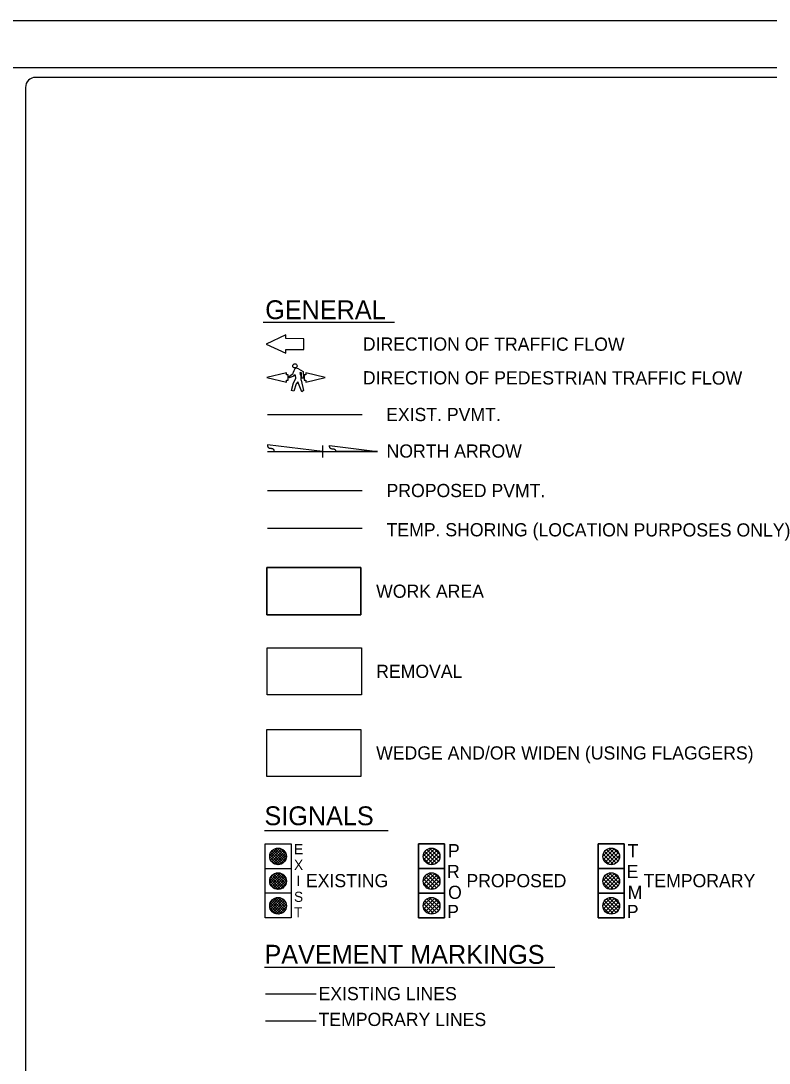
# Model space of a CAD drawing. Extents: x 0 to 1868, y 0 to 1100.
# Drawn here: x 733 to 1130, y 547 to 1100 of the extents above; entities that cross this region are included whole.
import ezdxf

# ---------------------------------------------------------------- set-up
doc = ezdxf.new("R2010")
doc.units = 0
for name, color, linetype in [('Exist Utilities Power Test Hole SUE LOS A CELL', 7, 'Continuous'), ('Exist Utilities Sanitary Sewer Test Hole SUE LOS A CELL', 7, 'Continuous'), ('Exist Utilities Telephone Test Hole SUE LOS A CELL', 7, 'Continuous'), ('P_RDY_Easement_Permanent_Drainage_Utility', 7, 'Continuous'), ('P_RDY_ROW_Permanent_Easement_CELL', 7, 'Continuous'), ('P_RDY_WCC_CELL', 7, 'Continuous')]:
    doc.layers.add(name, color=color, linetype=linetype)

msp = doc.modelspace()

# ---------------------------------------------------------------- linework, layer by layer
at = {"layer": 'Exist Utilities Power Test Hole SUE LOS A CELL'}
for p, q in [((862.52, 663.4), (876.32, 663.4)), ((862.52, 650.3), (862.52, 663.4)), ((864.99, 657.02), (869.1, 661.12)), ((865.09, 655.7), (870.41, 661.02)), ((865.47, 654.67), (871.45, 660.64)), ((865.52, 658.81), (871.53, 652.8)), ((865.73, 659.17), (866.95, 660.38)), ((866.04, 653.82), (872.3, 660.08)), ((866.1, 659.64), (872.36, 653.38)), ((866.77, 653.14), (872.98, 659.35)), ((866.84, 660.31), (873.03, 654.12)), ((867.67, 652.62), (873.5, 658.45)), ((867.76, 660.81), (873.53, 655.04)), ((868.88, 661.1), (873.82, 656.16)), ((870.36, 661.03), (873.75, 657.65)), ((876.32, 663.4), (876.32, 650.3)), ((864.98, 656.52), (869.23, 652.26)), ((865.12, 657.8), (870.52, 652.4)), ((865.54, 654.55), (867.27, 652.82)), ((868.77, 652.31), (873.81, 657.35)), ((870.21, 652.33), (873.79, 655.91)), ((862.52, 650.3), (876.32, 650.3)), ((862.52, 637.2), (862.52, 650.3)), ((864.98, 643.64), (869.38, 648.04)), ((865.15, 642.39), (870.62, 647.87)), ((865.39, 645.47), (867.55, 647.62)), ((865.57, 641.4), (871.62, 647.45)), ((867.04, 647.34), (873.16, 641.22)), ((867.99, 647.8), (873.62, 642.17)), ((869.18, 648.03), (873.85, 643.36)), ((870.81, 647.81), (873.63, 644.99)), ((876.32, 650.3), (876.32, 637.2)), ((864.98, 643.74), (869.56, 639.16)), ((865.19, 644.94), (870.76, 639.37)), ((865.26, 642.04), (867.86, 639.44)), ((865.63, 645.92), (871.74, 639.81)), ((866.16, 640.58), (872.44, 646.85)), ((866.25, 646.71), (872.53, 640.43)), ((866.93, 639.93), (873.09, 646.09)), ((867.86, 639.44), (873.57, 645.16)), ((869.01, 639.18), (873.84, 644.01)), ((870.55, 639.31), (873.71, 642.47)), ((876.32, 637.2), (862.52, 637.2)), ((862.52, 624.1), (862.52, 637.2)), ((876.32, 637.2), (876.32, 624.1)), ((864.99, 630.84), (869.76, 626.07)), ((865.01, 631), (868.92, 634.91)), ((865.06, 629.64), (870.27, 634.85)), ((865.24, 632), (870.92, 626.32)), ((865.42, 628.58), (871.34, 634.5)), ((865.72, 632.94), (871.86, 626.8)), ((865.96, 627.71), (872.2, 633.95)), ((866.36, 633.71), (872.63, 627.44)), ((866.68, 627.01), (872.91, 633.24)), ((867.17, 634.32), (873.24, 628.25)), ((867.55, 626.47), (873.44, 632.37)), ((868.15, 634.75), (873.67, 629.23)), ((868.63, 626.13), (873.78, 631.29)), ((869.38, 634.94), (873.86, 630.46)), ((871.14, 634.59), (873.51, 632.22)), ((865.16, 629.26), (868.18, 626.24)), ((870.01, 626.1), (873.82, 629.91)), ((876.32, 624.1), (862.52, 624.1))]:
    msp.add_line(p, q, dxfattribs=at)
for centre in [(869.42, 656.7), (869.42, 643.6), (869.42, 630.5)]:
    msp.add_circle(centre, 4.44, dxfattribs=at)
at = {"layer": 'Exist Utilities Sanitary Sewer Test Hole SUE LOS A CELL'}
msp.add_lwpolyline([(0, 0), (1688, 0), (1688, 1100), (0, 1100)], close=True, dxfattribs=at)
at = {"layer": 'Exist Utilities Telephone Test Hole SUE LOS A CELL'}
msp.add_line((862.82, 583.78), (889.62, 583.78), dxfattribs=at)
at = {"layer": 'P_RDY_Easement_Permanent_Drainage_Utility'}
msp.add_line((863.81, 830.84), (914, 830.84), dxfattribs=at)
at = {"layer": 'P_RDY_ROW_Permanent_Easement_CELL'}
for p, q in [((1652.71, 1075), (173.28, 1075)), ((1652.71, 1070), (740.76, 1070)), ((735.48, 1064.72), (735.48, 35.28)), ((861.5, 940.08), (931.19, 940.08)), ((873.53, 933.35), (863.18, 928.49)), ((873.52, 931.38), (873.53, 933.35)), ((883.12, 931.37), (873.52, 931.38)), ((883.12, 925.58), (883.12, 931.37)), ((863.18, 928.49), (873.52, 923.61)), ((873.52, 923.61), (873.52, 925.58)), ((873.52, 925.58), (883.12, 925.58)), ((873.86, 913.18), (863.52, 910.75)), ((873.86, 912.19), (873.86, 913.18)), ((875.03, 911.21), (877.52, 912.84)), ((877.52, 912.84), (877.68, 913.83)), ((880.31, 915.36), (882.81, 913.87)), ((881.9, 913.22), (881.09, 913.38)), ((882.13, 910.4), (881.9, 913.22)), ((882.81, 913.87), (882.84, 910.4)), ((894.47, 910.74), (884.14, 913.18)), ((884.14, 913.18), (884.14, 912.19)), ((863.52, 910.75), (873.85, 908.31)), ((873.85, 908.31), (873.85, 909.3)), ((873.85, 909.3), (874.78, 909.29)), ((874.79, 912.19), (873.86, 912.19)), ((874.78, 909.29), (874.79, 912.19)), ((875.42, 910.66), (875.03, 911.21)), ((877.7, 911.41), (875.42, 910.66)), ((876.52, 903.95), (877.59, 908.01)), ((877.59, 908.01), (878.82, 910.27)), ((878.48, 912.13), (877.7, 911.41)), ((879.02, 907.45), (877.85, 903.53)), ((879.99, 908.43), (879.02, 907.45)), ((881.96, 903.24), (879.99, 908.43)), ((881.66, 909.33), (882.94, 903.92)), ((882.84, 910.4), (882.13, 910.4)), ((884.14, 912.19), (883.2, 912.19)), ((883.2, 912.19), (883.2, 909.3)), ((883.2, 909.3), (884.13, 909.29)), ((884.13, 908.31), (894.47, 910.74)), ((884.13, 909.29), (884.13, 908.31)), ((877.85, 903.53), (876.52, 903.95)), ((882.94, 903.92), (881.96, 903.24)), ((863.81, 891.19), (914.01, 891.15)), ((893.04, 871.48), (863.82, 875.07)), ((893.04, 874.62), (893.04, 868.35)), ((896.76, 874.61), (922.27, 871.48)), ((863.82, 871.48), (922.27, 871.48)), ((867.28, 871.49), (893.04, 871.48)), ((922.27, 871.48), (900.07, 871.49)), ((863.81, 850.87), (914, 850.83)), ((863.4, 724.09), (913.4, 724.09)), ((863.4, 699.09), (863.4, 724.09)), ((913.4, 699.09), (863.4, 699.09)), ((862.2, 670.41), (927.79, 670.41)), ((946.5, 656.8), (950.8, 661.1)), ((946.85, 655), (952.6, 660.8)), ((953.5, 653.15), (947.35, 659.25)), ((947.65, 653.7), (953.9, 659.95)), ((954.55, 654.2), (948.4, 660.35)), ((948.85, 652.8), (954.8, 658.7)), ((955.2, 655.65), (949.85, 661)), ((955.15, 657.8), (952.05, 660.95)), ((1041.78, 656.8), (1046.08, 661.1)), ((1042.13, 655), (1047.88, 660.8)), ((1048.78, 653.15), (1042.63, 659.25)), ((1042.93, 653.7), (1049.18, 659.95)), ((1049.83, 654.2), (1043.68, 660.35)), ((1044.13, 652.8), (1050.08, 658.7)), ((1050.48, 655.65), (1045.13, 661)), ((1050.43, 657.8), (1047.33, 660.95)), ((950, 652.35), (946.6, 655.8)), ((952.05, 652.45), (946.65, 657.85)), ((950.5, 652.35), (955.3, 657.1)), ((953.4, 653.1), (954.65, 654.35)), ((1045.28, 652.35), (1041.88, 655.8)), ((1047.33, 652.45), (1041.93, 657.85)), ((1045.78, 652.35), (1050.58, 657.1)), ((1048.68, 653.1), (1049.93, 654.35)), ((946.5, 643.7), (950.8, 648)), ((946.85, 641.9), (952.6, 647.7)), ((954.55, 641.1), (948.4, 647.25)), ((955.2, 642.55), (949.85, 647.9)), ((955.15, 644.7), (952.05, 647.85)), ((1041.78, 643.7), (1046.08, 648)), ((1042.13, 641.9), (1047.88, 647.7)), ((1049.83, 641.1), (1043.68, 647.25)), ((1050.48, 642.55), (1045.13, 647.9)), ((1050.43, 644.7), (1047.33, 647.85)), ((950, 639.25), (946.6, 642.7)), ((952.05, 639.35), (946.65, 644.75)), ((953.5, 640.05), (947.35, 646.15)), ((947.65, 640.6), (953.9, 646.85)), ((948.85, 639.7), (954.8, 645.6)), ((950.5, 639.25), (955.3, 644)), ((1045.28, 639.25), (1041.88, 642.7)), ((1047.33, 639.35), (1041.93, 644.75)), ((1048.78, 640.05), (1042.63, 646.15)), ((1042.93, 640.6), (1049.18, 646.85)), ((1044.13, 639.7), (1050.08, 645.6)), ((1045.78, 639.25), (1050.58, 644)), ((953.4, 640), (954.65, 641.25)), ((1048.68, 640), (1049.93, 641.25)), ((946.5, 630.6), (950.8, 634.9)), ((952.05, 626.25), (946.65, 631.65)), ((946.85, 628.8), (952.6, 634.6)), ((953.5, 626.95), (947.35, 633.05)), ((947.65, 627.5), (953.9, 633.75)), ((954.55, 628), (948.4, 634.15)), ((948.85, 626.6), (954.8, 632.5)), ((955.2, 629.45), (949.85, 634.8)), ((950.5, 626.15), (955.3, 630.9)), ((955.15, 631.6), (952.05, 634.75)), ((1041.78, 630.6), (1046.08, 634.9)), ((1047.33, 626.25), (1041.93, 631.65)), ((1042.13, 628.8), (1047.88, 634.6)), ((1048.78, 626.95), (1042.63, 633.05)), ((1042.93, 627.5), (1049.18, 633.75)), ((1049.83, 628), (1043.68, 634.15)), ((1044.13, 626.6), (1050.08, 632.5)), ((1050.48, 629.45), (1045.13, 634.8)), ((1045.78, 626.15), (1050.58, 630.9)), ((1050.43, 631.6), (1047.33, 634.75)), ((950, 626.15), (946.6, 629.6)), ((953.4, 626.9), (954.65, 628.15)), ((1045.28, 626.15), (1041.88, 629.6)), ((1048.68, 626.9), (1049.93, 628.15)), ((862.2, 597.86), (1016.32, 597.86)), ((862.82, 569.38), (889.62, 569.38))]:
    msp.add_line(p, q, dxfattribs=at)
for points in [[(913.4, 809.89), (863.4, 809.89), (863.4, 784.89), (913.4, 784.89)], [(863.4, 809.89), (913.4, 809.89), (913.4, 784.89), (863.4, 784.89)], [(863.62, 767.38), (913.62, 767.38), (913.62, 742.38), (863.62, 742.38)], [(863.62, 767.38), (913.62, 767.38), (913.62, 742.38), (863.62, 742.38)], [(863.62, 767.38), (913.62, 767.38), (913.62, 742.38), (863.62, 742.38)], [(863.4, 724.09), (913.4, 724.09), (913.4, 699.09), (863.4, 699.09)], [(863.4, 724.09), (913.4, 724.09), (913.4, 699.09), (863.4, 699.09)], [(944, 650.3), (957.8, 650.3), (957.8, 663.4), (944, 663.4)], [(1039.28, 650.3), (1053.08, 650.3), (1053.08, 663.4), (1039.28, 663.4)], [(944, 637.2), (957.8, 637.2), (957.8, 650.3), (944, 650.3)], [(1039.28, 637.2), (1053.08, 637.2), (1053.08, 650.3), (1039.28, 650.3)], [(944, 624.1), (957.8, 624.1), (957.8, 637.2), (944, 637.2)], [(1039.28, 624.1), (1053.08, 624.1), (1053.08, 637.2), (1039.28, 637.2)]]:
    msp.add_lwpolyline(points, close=True, dxfattribs=at)
for centre, radius in [((878.37, 916.95), 1.11), ((950.9, 656.7), 4.44), ((1046.18, 656.7), 4.44), ((950.9, 643.6), 4.44), ((1046.18, 643.6), 4.44), ((950.9, 630.5), 4.44), ((1046.18, 630.5), 4.44)]:
    msp.add_circle(centre, radius, dxfattribs=at)
for centre, radius, start, end in [((740.76, 1064.72), 5.29, 89.9972, 180), ((880.85, 913.3), 3.22, 140.1678, 170.5556), ((879.03, 914.82), 0.84, 96.8806, 140.1678), ((879.19, 913.48), 2.19, 59.1458, 96.8806), ((873.41, 910.25), 8.29, 353.6356, 22.2339), ((873.41, 910.25), 5.41, 0.2881, 20.3672)]:
    msp.add_arc(centre, radius, start, end, dxfattribs=at)
for points in [[(863.82, 875.07), (863.73, 873.26), (867.3, 873.2), (867.28, 871.49)], [(900.07, 871.48), (900.24, 872.74), (896.67, 872.8), (896.76, 874.61)]]:
    msp.add_open_spline(points, degree=2, dxfattribs=at)
at = {"layer": 'P_RDY_WCC_CELL'}
for points in [[(863.4, 784.89), (913.4, 784.89), (913.4, 809.89), (863.4, 809.89)], [(944, 663.4), (957.8, 663.4), (957.8, 624.1), (944, 624.1)], [(1039.28, 663.4), (1053.08, 663.4), (1053.08, 624.1), (1039.28, 624.1)]]:
    msp.add_lwpolyline(points, close=True, dxfattribs=at)

# ---------------------------------------------------------------- texts
at = {"layer": 'Exist Utilities Power Test Hole SUE LOS A CELL'}
for s, p in [('E', (877.91, 657.83)), ('X', (877.91, 649.49)), ('I', (879.17, 641.05)), ('S', (877.91, 632.57)), ('T', (877.91, 624.31))]:
    msp.add_text(s, height=5.4, dxfattribs=at).set_placement(p)
at = {"layer": 'P_RDY_ROW_Permanent_Easement_CELL'}
for s, height, rotation, p in [('GENERAL', 10, 359.9598, (862.61, 941.73)), ('DIRECTION OF TRAFFIC FLOW', 7, 359.9598, (914.41, 925.04)), ('DIRECTION OF PEDESTRIAN TRAFFIC FLOW', 7, 359.9598, (914.41, 907.14)), ('EXIST. PVMT.', 7, 359.9598, (926.74, 887.65)), ('NORTH ARROW', 7, 359.9598, (926.99, 868.28)), ('PROPOSED PVMT.', 7, 359.9598, (926.97, 847.33)), ('TEMP. SHORING (LOCATION PURPOSES ONLY)', 7, 359.9598, (926.97, 826.53)), ('WORK AREA', 7, 360, (921.46, 793.89)), ('REMOVAL', 7, 360, (921.46, 751.38)), ('WEDGE AND/OR WIDEN (USING FLAGGERS)', 7, 360, (921.46, 708.09)), ('SIGNALS', 10, 359.9598, (862.21, 673.26)), ('EXISTING', 7, 359.9598, (884.21, 640.35)), ('PROPOSED', 7, 359.9598, (969.35, 640.35)), ('TEMPORARY ', 7, 359.9598, (1063.33, 640.36)), ('PAVEMENT MARKINGS', 10, 359.9598, (862.21, 599.78)), ('EXISTING LINES', 7, 359.9598, (890.91, 580.41)), ('TEMPORARY LINES', 7, 359.9598, (890.91, 566.74))]:
    msp.add_text(s, height=height, rotation=rotation, dxfattribs=at).set_placement(p)
for s, p in [('P', (959.55, 656.23)), ('T', (1054.83, 656.23)), ('R', (959.06, 645.18)), ('E', (1054.35, 645.18)), ('E', (1054.35, 645.18)), ('O', (959.62, 634.14)), ('M', (1054.9, 634.14)), ('P', (959.13, 623.96)), ('P', (1054.42, 623.96)), ('P', (1054.42, 623.96))]:
    msp.add_text(s, height=7, dxfattribs=at).set_placement(p)

doc.saveas('drawing.dxf')
